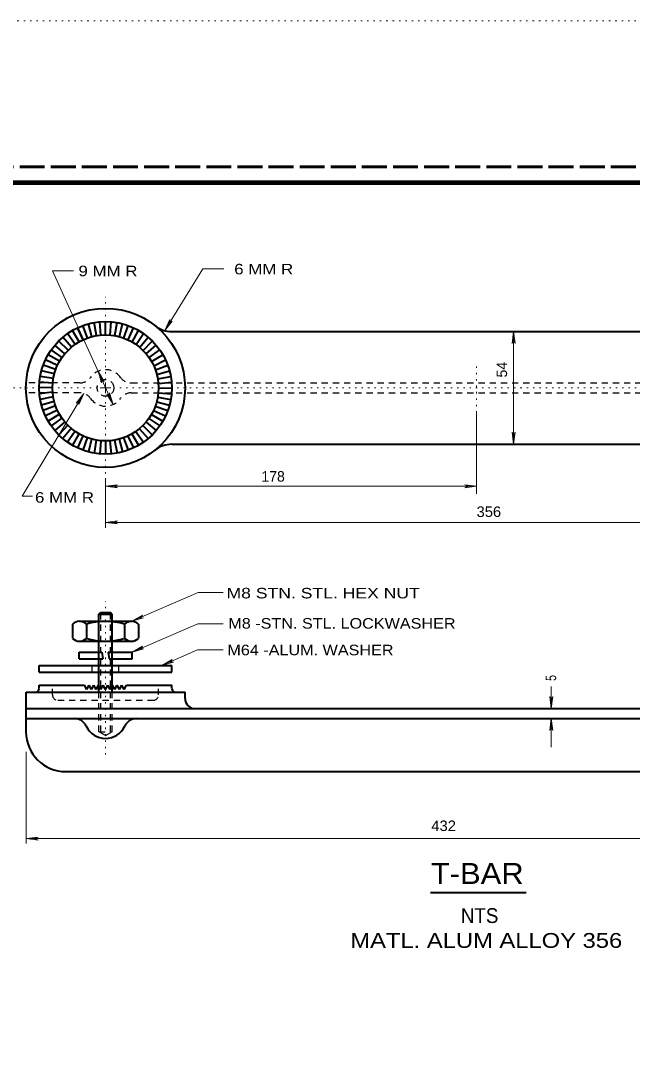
# Model space of a CAD drawing. Extents: x 312583 to 312854, y 144419 to 144597.
# Drawn here: x 312692.5 to 312736.7, y 144521.9 to 144596.8 of the extents above; entities that cross this region are included whole.
import ezdxf
from ezdxf.enums import TextEntityAlignment as Align

# ---------------------------------------------------------------- set-up
doc = ezdxf.new("R2010")
doc.units = 0
doc.header["$LTSCALE"] = 0.3
for name, pattern in [('DOTTED', [1.5, 0.3, -1.2]), ('LONG_DASHED', [7.5, 6, -1.5]), ('SHORT_DASHED', [2.7, 1.5, -1.2])]:
    doc.linetypes.add(name, pattern=pattern)
for name, color, linetype, lineweight in [('1', 7, 'Continuous', 40), ('2', 7, 'Continuous', 13), ('62', 7, 'DOTTED', 13), ('63', 7, 'LONG_DASHED', 60)]:
    doc.layers.add(name, color=color, linetype=linetype, lineweight=lineweight)

msp = doc.modelspace()

# ---------------------------------------------------------------- linework, layer by layer
at = {"layer": '1'}
for p, q in [((312697.6707, 144573.9575), (312697.4177, 144574.8775)), ((312697.9927, 144574.0265), (312697.824, 144574.9695)), ((312698.3223, 144574.0725), (312698.238, 144575.0232)), ((312698.6597, 144574.0878), (312698.6597, 144575.0462)), ((312699.0047, 144574.0725), (312699.0737, 144575.0232)), ((312699.342, 144574.0265), (312699.4877, 144574.9695)), ((312699.664, 144573.9575), (312699.894, 144574.8775)), ((312696.4593, 144573.3978), (312695.9073, 144574.1722)), ((312696.743, 144573.5742), (312696.26, 144574.4022)), ((312697.042, 144573.7275), (312696.6357, 144574.5938)), ((312697.3487, 144573.8578), (312697.019, 144574.7548)), ((312699.986, 144573.8502), (312700.2927, 144574.7548)), ((312700.2927, 144573.7198), (312700.6837, 144574.5938)), ((312700.5917, 144573.5665), (312701.0517, 144574.4022)), ((312700.8677, 144573.3825), (312701.4043, 144574.1722)), ((312703.4437, 144574.3255), (312747.5423, 144574.3255)), ((312695.9533, 144572.9685), (312695.271, 144573.6355)), ((312696.1987, 144573.1908), (312695.5777, 144573.9192)), ((312701.136, 144573.1832), (312701.734, 144573.9192)), ((312701.3813, 144572.9532), (312702.0407, 144573.6355)), ((312695.34, 144572.1788), (312694.512, 144572.6465)), ((312695.524, 144572.4548), (312694.7343, 144572.9992)), ((312695.7233, 144572.7232), (312694.9873, 144573.3288)), ((312701.6037, 144572.7078), (312702.3243, 144573.3288)), ((312701.8107, 144572.4395), (312702.5773, 144572.9992)), ((312701.987, 144572.1558), (312702.8073, 144572.6465)), ((312695.0563, 144571.5732), (312694.1593, 144571.8875)), ((312695.1867, 144571.8798), (312694.3203, 144572.2785)), ((312702.1403, 144571.8568), (312702.999, 144572.2785)), ((312702.2707, 144571.5502), (312703.16, 144571.8875)), ((312694.9567, 144571.2588), (312694.029, 144571.4888)), ((312702.3703, 144571.2282), (312703.2827, 144571.4888)), ((312694.8417, 144570.5995), (312693.8833, 144570.6685)), ((312694.8877, 144570.9292), (312693.937, 144571.0825)), ((312702.4393, 144570.9062), (312703.3747, 144571.0825)), ((312702.4853, 144570.5688), (312703.4283, 144570.6685)), ((312694.8263, 144570.2698), (312693.868, 144570.2545)), ((312694.834, 144569.9325), (312693.8833, 144569.8328)), ((312694.88, 144569.6028), (312693.937, 144569.4188)), ((312702.4777, 144569.9018), (312703.4283, 144569.8328)), ((312702.493, 144570.2392), (312703.4513, 144570.2545)), ((312694.949, 144569.2732), (312694.029, 144569.0125)), ((312695.0487, 144568.9588), (312694.1593, 144568.6138)), ((312702.2553, 144568.9282), (312703.16, 144568.6138)), ((312702.3627, 144569.2425), (312703.2827, 144569.0125)), ((312702.4317, 144569.5722), (312703.3747, 144569.4188)), ((312695.179, 144568.6445), (312694.3203, 144568.2305)), ((312695.3323, 144568.3455), (312694.512, 144567.8548)), ((312701.9717, 144568.3225), (312702.8073, 144567.8548)), ((312702.125, 144568.6138), (312702.999, 144568.2305)), ((312695.5087, 144568.0618), (312694.7343, 144567.5022)), ((312695.7157, 144567.8012), (312694.9873, 144567.1725)), ((312695.938, 144567.5482), (312695.271, 144566.8658)), ((312701.3583, 144567.5328), (312702.0407, 144566.8658)), ((312701.5883, 144567.7782), (312702.3243, 144567.1725)), ((312701.7877, 144568.0388), (312702.5773, 144567.5022)), ((312696.1833, 144567.3258), (312695.5777, 144566.5822)), ((312696.4517, 144567.1188), (312695.9073, 144566.3292)), ((312696.7277, 144566.9425), (312696.26, 144566.1068)), ((312697.0267, 144566.7815), (312696.6357, 144565.9152)), ((312697.3333, 144566.6512), (312697.019, 144565.7542)), ((312699.9553, 144566.6435), (312700.2927, 144565.7542)), ((312700.262, 144566.7662), (312700.6837, 144565.9152)), ((312700.561, 144566.9195), (312701.0517, 144566.1068)), ((312700.8447, 144567.1035), (312701.4043, 144566.3292)), ((312701.113, 144567.3028), (312701.734, 144566.5822)), ((312697.6477, 144566.5515), (312697.4177, 144565.6238)), ((312697.9773, 144566.4748), (312697.824, 144565.5318)), ((312698.307, 144566.4288), (312698.238, 144565.4782)), ((312698.6443, 144566.4135), (312698.6597, 144565.4628)), ((312698.974, 144566.4288), (312699.0737, 144565.4782)), ((312699.3113, 144566.4672), (312699.4877, 144565.5318)), ((312699.6333, 144566.5438), (312699.894, 144565.6238)), ((312703.4437, 144566.1835), (312747.5423, 144566.1835)), ((312698.1767, 144553.9092), (312698.2993, 144554.0318)), ((312698.1767, 144553.9092), (312699.135, 144553.9092)), ((312698.1767, 144548.2742), (312698.1767, 144553.9092)), ((312698.2993, 144554.0318), (312699.0123, 144554.0318)), ((312699.135, 144553.9092), (312699.0123, 144554.0318)), ((312699.135, 144548.2742), (312699.135, 144553.9092)), ((312696.26, 144553.1808), (312696.26, 144552.1535)), ((312696.743, 144553.3878), (312700.5687, 144553.3878)), ((312697.2873, 144553.1808), (312697.2873, 144552.1535)), ((312700.032, 144553.1808), (312700.032, 144552.1535)), ((312701.0517, 144553.1808), (312701.0517, 144552.1535)), ((312696.743, 144551.9465), (312700.5687, 144551.9465)), ((312696.743, 144550.6738), (312696.743, 144551.1492)), ((312696.743, 144551.1492), (312698.3913, 144551.1492)), ((312698.3913, 144551.1492), (312698.468, 144550.6738)), ((312698.8437, 144551.1492), (312698.9203, 144550.6738)), ((312698.8437, 144551.1492), (312700.5763, 144551.1492)), ((312700.5763, 144550.6738), (312700.5763, 144551.1492)), ((312693.868, 144549.7155), (312693.868, 144550.1908)), ((312693.868, 144550.1908), (312703.4513, 144550.1908)), ((312696.743, 144550.6738), (312698.468, 144550.6738)), ((312698.9203, 144550.6738), (312700.5763, 144550.6738)), ((312703.4513, 144549.7155), (312703.4513, 144550.1908)), ((312693.868, 144549.7155), (312703.4513, 144549.7155)), ((312693.868, 144548.5195), (312693.868, 144548.7572)), ((312693.868, 144548.7572), (312697.1417, 144548.7572)), ((312697.3103, 144548.4658), (312697.1417, 144548.7572)), ((312697.3103, 144548.4658), (312697.479, 144548.7572)), ((312697.6477, 144548.4658), (312697.479, 144548.7572)), ((312697.6477, 144548.4658), (312697.8163, 144548.7572)), ((312697.985, 144548.4658), (312697.8163, 144548.7572)), ((312697.985, 144548.4658), (312698.1537, 144548.7572)), ((312698.3223, 144548.4658), (312698.1537, 144548.7572)), ((312698.3223, 144548.4658), (312698.491, 144548.7572)), ((312698.6597, 144548.4658), (312698.491, 144548.7572)), ((312698.6597, 144548.4658), (312698.8283, 144548.7572)), ((312698.997, 144548.4658), (312698.8283, 144548.7572)), ((312698.997, 144548.4658), (312699.1657, 144548.7572)), ((312699.3343, 144548.4658), (312699.1657, 144548.7572)), ((312699.3343, 144548.4658), (312699.503, 144548.7572)), ((312699.6717, 144548.4658), (312699.503, 144548.7572)), ((312699.6717, 144548.4658), (312699.8403, 144548.7572)), ((312700.009, 144548.4658), (312699.8403, 144548.7572)), ((312700.009, 144548.4658), (312700.1777, 144548.7572)), ((312700.1777, 144548.7572), (312703.4513, 144548.7572)), ((312703.4513, 144548.5195), (312703.4513, 144548.7572)), ((312692.9097, 144545.3992), (312692.9097, 144548.2742)), ((312692.9097, 144548.2742), (312704.4097, 144548.2742)), ((312704.4097, 144547.7988), (312704.4097, 144548.2742)), ((312692.9097, 144547.0782), (312745.8557, 144547.0782)), ((312692.9097, 144546.3575), (312758.0763, 144546.3575)), ((312695.7847, 144542.5242), (312755.2013, 144542.5242))]:
    msp.add_line(p, q, dxfattribs=at)
at = {"layer": '1', "linetype": 'DOTTED', "lineweight": 13}
for p, q in [((312725.493, 144568.4758), (312725.493, 144572.0102)), ((312698.6597, 144543.7585), (312698.6597, 144554.8215))]:
    msp.add_line(p, q, dxfattribs=at)
at = {"layer": '1', "linetype": 'SHORT_DASHED', "lineweight": 25}
for p, q in [((312696.8043, 144570.6148), (312692.9173, 144570.6148)), ((312700.515, 144570.6148), (312750.471, 144570.6148)), ((312696.8043, 144569.8942), (312692.9173, 144569.8942)), ((312700.515, 144569.8942), (312750.471, 144569.8942)), ((312698.307, 144545.4068), (312698.307, 144554.0318)), ((312699.0123, 144545.4068), (312699.0123, 144554.0318)), ((312697.7013, 144549.7155), (312697.7013, 144550.1908)), ((312699.618, 144549.7155), (312699.618, 144550.1908)), ((312694.8263, 144548.0595), (312694.8263, 144548.7572)), ((312702.493, 144548.0595), (312702.493, 144548.7572)), ((312698.1767, 144545.4068), (312698.1767, 144548.2742)), ((312699.135, 144545.4068), (312699.135, 144548.2742)), ((312695.2097, 144547.6762), (312702.1097, 144547.6762)), ((312698.1767, 144545.4068), (312699.135, 144545.4068)), ((312698.6597, 144545.1308), (312698.1767, 144545.4068)), ((312698.6597, 144545.1308), (312699.135, 144545.4068))]:
    msp.add_line(p, q, dxfattribs=at)
at = {"layer": '1', "lineweight": 158}
msp.add_lwpolyline([(312616.5, 144423.1446), (312616.5, 144585.0846), (312849, 144585.0846)], dxfattribs=at)
at = {"layer": '1'}
for radius in [5.75, 4.7917, 3.8333]:
    msp.add_circle((312698.6558, 144570.2507), radius, dxfattribs=at)
at = {"layer": '1', "linetype": 'SHORT_DASHED', "lineweight": 25}
msp.add_circle((312698.6558, 144570.2507), 0.599, dxfattribs=at)
at = {"layer": '1'}
for centre, radius, start, end in [((312703.4391, 144576.2422), 1.9167, 231.39812, 270), ((312703.4391, 144564.2592), 1.9167, 90, 128.60188), ((312693.6246, 144548.5137), 0.2396, 270, 0), ((312703.6871, 144548.5137), 0.2396, 180, 270), ((312705.1246, 144547.7969), 0.7188, 180, 270), ((312696.3981, 144545.3992), 0.9583, 25.029, 90), ((312698.6558, 144546.4533), 1.5333, 205.029, 334.971), ((312700.9135, 144545.3992), 0.9583, 90, 154.971), ((312695.7808, 144545.3992), 2.875, 180, 270)]:
    msp.add_arc(centre, radius, start, end, dxfattribs=at)
at = {"layer": '1', "linetype": 'SHORT_DASHED', "lineweight": 25}
for centre, radius, start, end in [((312698.6558, 144570.2507), 1.3177, 35.40195, 144.59805), ((312696.8007, 144571.5693), 0.9583, 270, 324.59387), ((312700.511, 144571.5693), 0.9583, 215.40613, 270), ((312696.8007, 144568.932), 0.9583, 35.40613, 90), ((312700.511, 144568.932), 0.9583, 90, 144.59387), ((312698.6558, 144570.2507), 1.3177, 215.40195, 324.59805), ((312695.2058, 144548.0595), 0.3833, 180, 270), ((312702.1058, 144548.0595), 0.3833, 270, 0)]:
    msp.add_arc(centre, radius, start, end, dxfattribs=at)
at = {"layer": '1'}
for centre, major_axis, start_param, end_param in [((312696.7699, 144551.4016), (0, -1.9815), 2.6844324, 3.598753), ((312698.6529, 144539.6558), (0, -13.7273), 2.9691985, 3.3139868), ((312700.5339, 144551.4016), (0, -1.9815), 2.6844323, 3.598753), ((312696.7699, 144553.9272), (0, 1.9815), 2.6844323, 3.598753), ((312698.6529, 144565.673), (0, 13.7273), 2.9691985, 3.3139868), ((312700.5339, 144553.9272), (0, 1.9815), 2.6844324, 3.598753)]:
    msp.add_ellipse(centre, major_axis=major_axis, ratio=0.583066, start_param=start_param, end_param=end_param, dxfattribs=at)
at = {"layer": '2'}
for p, q in [((312699.204, 144569.0508), (312694.8187, 144578.7185)), ((312694.8187, 144578.7185), (312696.3521, 144578.7185)), ((312702.9377, 144574.3945), (312705.6977, 144578.8565)), ((312705.6977, 144578.8565), (312707.2233, 144578.8565)), ((312702.9377, 144574.3945), (312703.298, 144575.1918)), ((312702.9377, 144574.3945), (312703.482, 144575.0768)), ((312703.298, 144575.1918), (312703.2443, 144574.9005)), ((312703.482, 144575.0768), (312703.2443, 144574.9005)), ((312728.161, 144574.3255), (312728.0537, 144573.4592)), ((312728.161, 144566.1835), (312728.161, 144574.3255)), ((312728.161, 144574.3255), (312728.2683, 144573.4592)), ((312728.0537, 144573.4592), (312728.161, 144573.7352)), ((312728.2683, 144573.4592), (312728.161, 144573.7352)), ((312698.1153, 144571.4505), (312698.376, 144570.6225)), ((312698.1153, 144571.4505), (312698.5677, 144570.7068)), ((312698.376, 144570.6225), (312698.3607, 144570.9138)), ((312698.5677, 144570.7068), (312698.3607, 144570.9138)), ((312698.6597, 144570.2545), (312698.6597, 144570.6378)), ((312697.0803, 144569.8482), (312692.639, 144562.4224)), ((312697.0803, 144569.8482), (312696.5437, 144569.1582)), ((312697.0803, 144569.8482), (312696.7277, 144569.0508)), ((312698.6597, 144570.2545), (312698.2763, 144570.2545)), ((312698.6597, 144570.2545), (312699.043, 144570.2545)), ((312698.6597, 144570.2545), (312698.6597, 144569.8712)), ((312698.744, 144569.7945), (312698.9587, 144569.5875)), ((312699.204, 144569.0508), (312698.744, 144569.7945)), ((312698.9433, 144569.8865), (312698.9587, 144569.5875)), ((312699.204, 144569.0508), (312698.9433, 144569.8865)), ((312696.5437, 144569.1582), (312696.7737, 144569.3422)), ((312696.7277, 144569.0508), (312696.7737, 144569.3422)), ((312725.493, 144568.4758), (312725.493, 144562.5878)), ((312728.0537, 144567.0498), (312728.161, 144566.7738)), ((312728.161, 144566.1835), (312728.0537, 144567.0498)), ((312728.2683, 144567.0498), (312728.161, 144566.7738)), ((312728.161, 144566.1835), (312728.2683, 144567.0498)), ((312698.6597, 144563.7225), (312698.6597, 144560.1268)), ((312698.6597, 144563.1475), (312699.526, 144563.2548)), ((312698.6597, 144563.1475), (312725.493, 144563.1475)), ((312698.6597, 144563.1475), (312699.526, 144563.0402)), ((312699.526, 144563.2548), (312699.25, 144563.1475)), ((312699.526, 144563.0402), (312699.25, 144563.1475)), ((312724.6267, 144563.2548), (312724.9027, 144563.1475)), ((312725.493, 144563.1475), (312724.6267, 144563.2548)), ((312724.6267, 144563.0402), (312724.9027, 144563.1475)), ((312725.493, 144563.1475), (312724.6267, 144563.0402)), ((312693.3827, 144562.4224), (312692.639, 144562.4224)), ((312698.6597, 144560.5255), (312699.526, 144560.6328)), ((312699.526, 144560.6328), (312699.25, 144560.5255)), ((312698.6597, 144560.5255), (312752.3263, 144560.5255)), ((312698.6597, 144560.5255), (312699.526, 144560.4182)), ((312699.526, 144560.4182), (312699.25, 144560.5255)), ((312700.5687, 144553.3878), (312705.3527, 144555.4578)), ((312707.1543, 144555.4578), (312705.3527, 144555.4578)), ((312700.5687, 144553.3878), (312701.32, 144553.8248)), ((312700.5687, 144553.3878), (312701.4043, 144553.6332)), ((312700.5763, 144551.1492), (312705.322, 144553.2038)), ((312701.32, 144553.8248), (312701.1053, 144553.6178)), ((312701.4043, 144553.6332), (312701.1053, 144553.6178)), ((312707.1543, 144553.2038), (312705.322, 144553.2038)), ((312700.5763, 144551.1492), (312701.3277, 144551.5938)), ((312700.5763, 144551.1492), (312701.412, 144551.3945)), ((312701.3277, 144551.5938), (312701.113, 144551.3868)), ((312701.412, 144551.3945), (312701.113, 144551.3868)), ((312702.723, 144550.1908), (312705.299, 144551.3102)), ((312707.1543, 144551.3102), (312705.299, 144551.3102)), ((312702.723, 144550.1908), (312703.4743, 144550.6355)), ((312702.723, 144550.1908), (312703.5663, 144550.4362)), ((312703.4743, 144550.6355), (312703.2673, 144550.4285)), ((312703.5663, 144550.4362), (312703.2673, 144550.4285)), ((312730.8827, 144547.0782), (312730.8827, 144548.672)), ((312730.7753, 144547.9445), (312730.8827, 144547.6685)), ((312730.8827, 144547.0782), (312730.7753, 144547.9445)), ((312730.99, 144547.9445), (312730.8827, 144547.6685)), ((312730.8827, 144547.0782), (312730.99, 144547.9445)), ((312730.8827, 144546.3575), (312730.7753, 144545.4912)), ((312730.7753, 144545.4912), (312730.8827, 144545.7672)), ((312730.8827, 144544.2952), (312730.8827, 144546.3575)), ((312730.8827, 144546.3575), (312730.99, 144545.4912)), ((312730.99, 144545.4912), (312730.8827, 144545.7672)), ((312692.9097, 144543.9425), (312692.9097, 144537.3338)), ((312692.9097, 144537.6865), (312693.776, 144537.7938)), ((312692.9097, 144537.6865), (312758.0763, 144537.6865)), ((312692.9097, 144537.6865), (312693.776, 144537.5792)), ((312693.776, 144537.7938), (312693.5, 144537.6865)), ((312693.776, 144537.5792), (312693.5, 144537.6865))]:
    msp.add_line(p, q, dxfattribs=at)
at = {"layer": '2', "linetype": 'DOTTED'}
for p, q in [((312698.6597, 144570.8295), (312698.6597, 144576.8325)), ((312698.0847, 144570.2545), (312691.936, 144570.2545)), ((312698.6597, 144569.6795), (312698.6597, 144563.7225)), ((312699.2347, 144570.2545), (312725.0637, 144570.2545)), ((312751.7513, 144570.2545), (312725.0637, 144570.2545))]:
    msp.add_line(p, q, dxfattribs=at)
at = {"layer": '2', "lineweight": 40}
msp.add_line((312722.1615, 144533.7917), (312729.0696, 144533.7917), dxfattribs=at)
at = {"layer": '62'}
msp.add_line((312601.2, 144596.7846), (312853.5, 144596.7846), dxfattribs=at)
at = {"layer": '63'}
msp.add_line((312851.75, 144586.2246), (312583.526, 144586.2246), dxfattribs=at)

# ---------------------------------------------------------------- texts
at = {"layer": '2'}
for s, width, p in [('9 MM R', 1.2, (312696.6997, 144578.3201)), ('6 MM R', 1.2, (312707.9614, 144578.4564)), ('6 MM R', 1.2, (312693.5583, 144561.957)), ('356', 1.05, (312725.4845, 144560.9247)), ('M8 STN. STL. HEX NUT', 1.25, (312707.4073, 144555.0395)), ('M8 -STN. STL. LOCKWASHER', 1.15, (312707.5377, 144552.8545)), ('M64 -ALUM. WASHER', 1.15, (312707.4687, 144550.9302)), ('432', 1.05, (312722.216, 144538.2275))]:
    msp.add_text(s, height=0.76, dxfattribs=dict(at, width=width)).set_placement(p)
msp.add_text('54', height=0.76, rotation=90, dxfattribs=at).set_placement((312727.6913, 144571.0049))
msp.add_text('178', height=0.76, dxfattribs=at).set_placement((312709.9267, 144563.4758))
at = {"layer": '2', "width": 0.75}
msp.add_text('5', height=0.76, rotation=90, dxfattribs=at).set_placement((312731.2447, 144549.0788))
at = {"layer": '2'}
for s, height, width, p in [('T-BAR', 1.52, 1.1, (312725.5363, 144534.3988)), ('NTS', 1.07, 0.95, (312725.7075, 144531.5821)), ('MATL. ALUM ALLOY 356', 1.07, 1.2, (312726.188, 144529.7862))]:
    msp.add_text(s, height=height, dxfattribs=dict(at, width=width)).set_placement(p, align=Align.CENTER)

doc.saveas('drawing.dxf')
